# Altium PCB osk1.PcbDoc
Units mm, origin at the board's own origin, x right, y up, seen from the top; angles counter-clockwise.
Board outline 152.4 x 101.6 mm, 2 copper layers (Top Layer, Bottom Layer); 15 components, 15 nets, 59 pads, 0 vias.
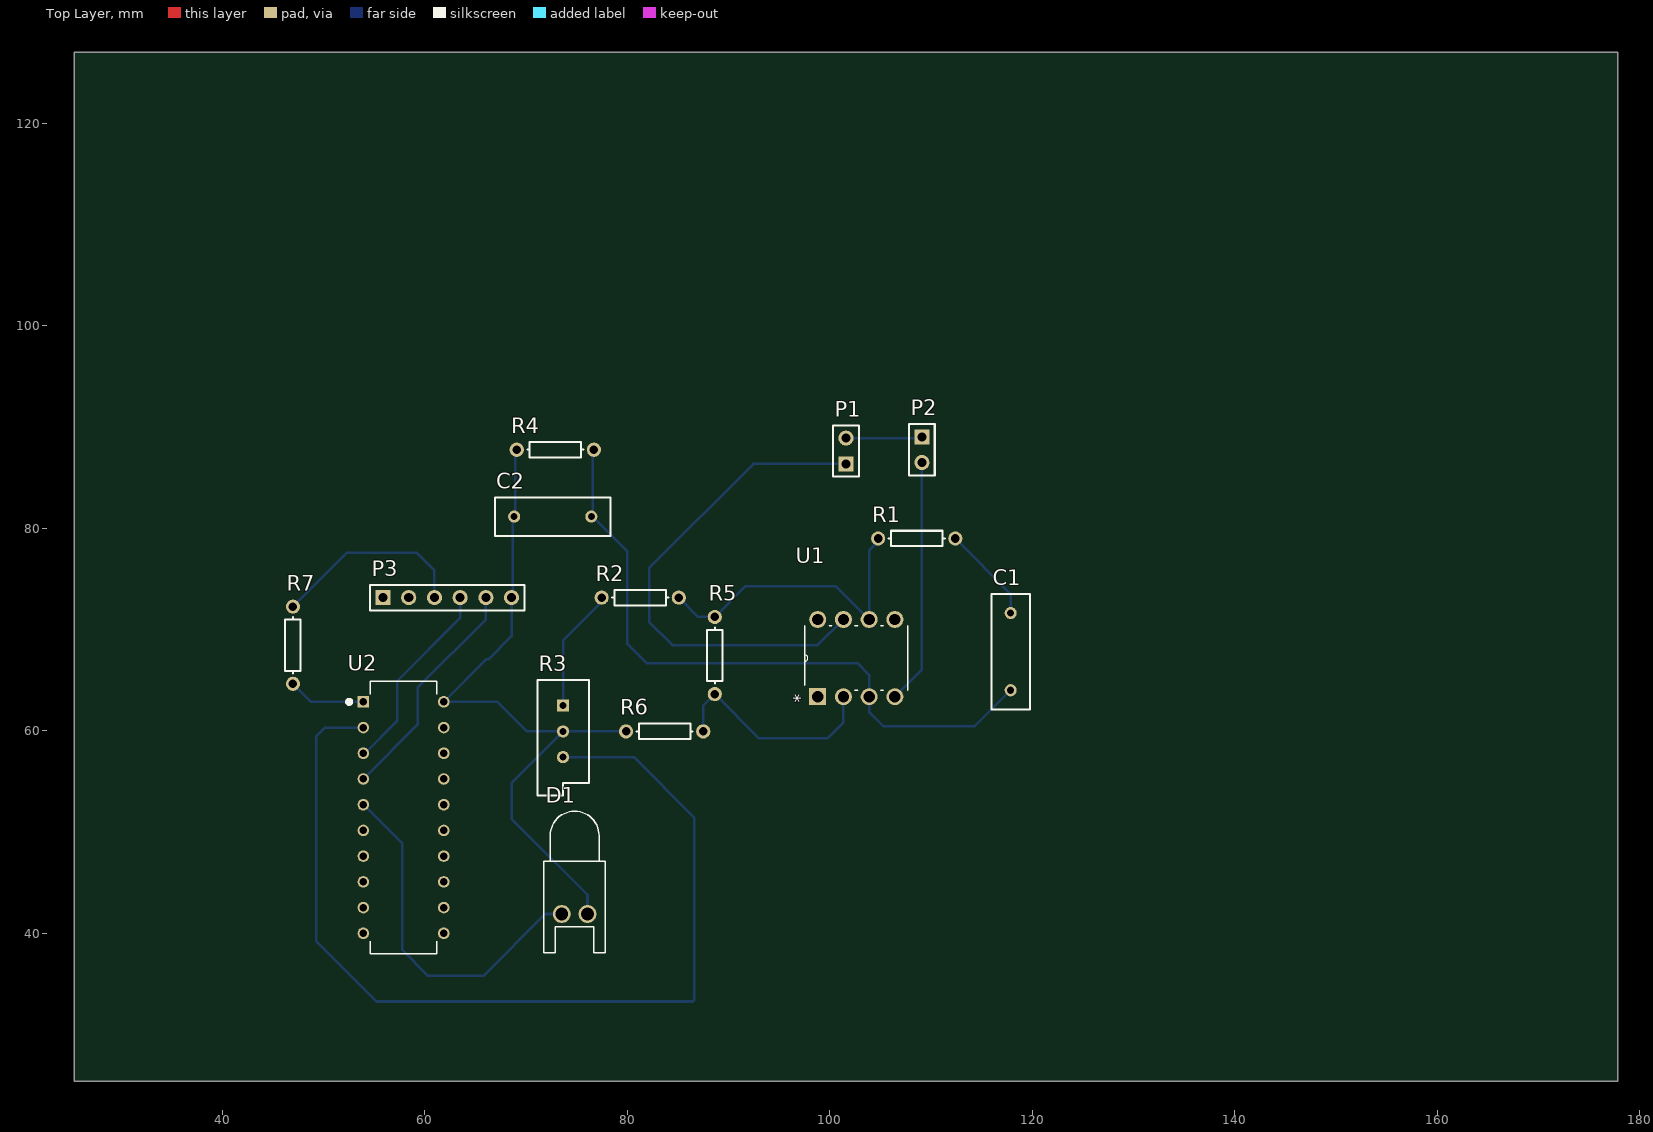
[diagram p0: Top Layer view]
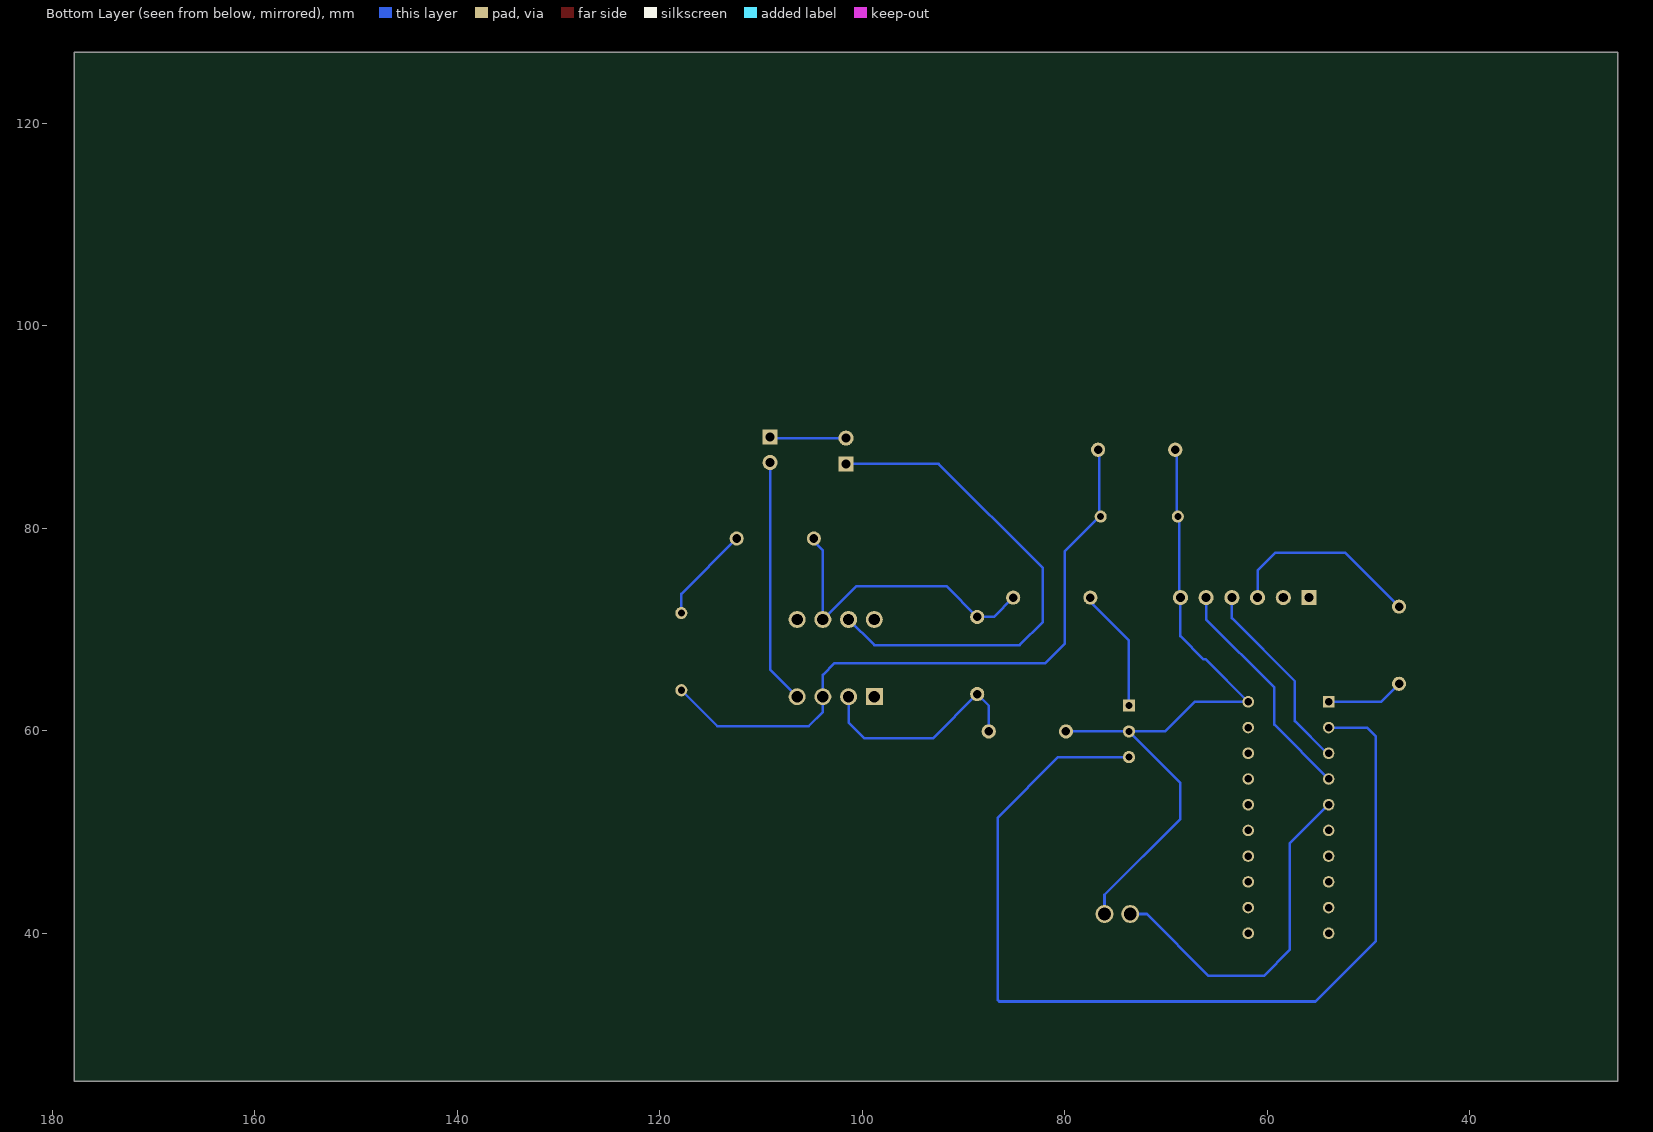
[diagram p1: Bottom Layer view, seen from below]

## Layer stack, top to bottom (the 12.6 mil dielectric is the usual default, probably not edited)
Top Solder: solder mask 0.0102, Solder Resist, Dk 3.5
Top Layer: signal copper 0.0356
Dielectric 1: dielectric 0.32, FR-4, Dk 4.8
Bottom Layer: signal copper 0.0356
Bottom Solder: solder mask 0.0102, Solder Resist, Dk 3.5

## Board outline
25.4,25.4 177.8,25.4 177.8,127 25.4,127

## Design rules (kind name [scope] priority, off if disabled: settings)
Clearance [All] p1: gap=0.254 ignorepadtopadclearanceinfootprint=FALSE except(0: Arc-Hole Track-Hole SMDPad-Hole THPad-Hole Via-Hole Fill-Hole Poly-Hole Region-Hole Text-Hole)
PolygonConnect [All] p1: connectstyle=Relief reliefconductorwidth=0.254 reliefentries=4 polygonreliefangle="90 Angle" airgapwidth=0.254
RoutingVias [All] p1: holewidth=0.711 width=1.27 viastyle="Through Hole" minholewidth=0.711 minwidth=1.27 maxholewidth=0.711 maxwidth=1.27
SolderMaskExpansion [All] p1: expansion=0.102 istentingtop=FALSE
Width [All] p1: maxlimit=0.254 minlimit=0.254 preferedwidth=0.254
30 further rules are at their usual default settings.

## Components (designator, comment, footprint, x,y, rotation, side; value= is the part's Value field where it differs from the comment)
C1 "Cap" RAD-0.3 117.856,67.818 r270 top value=1nF
C2 "Cap" RAD-0.3 72.644,81.153 r0 top value=1nF
D1 "LED0" LED-0 74.803,41.91 r180 top
P1 "Header 2" HDR1X2 101.6,86.36 r90 top
P2 "Header 2" HDR1X2 109.093,89.027 r270 top
P3 "Header 6" HDR1X6 55.88,73.152 r0 top
R1 "Res1" AXIAL-0.3 108.585,78.994 r0 top value=100K
R2 "Res1" AXIAL-0.3 81.28,73.152 r180 top value=2.2K
R3 "RPot" VR5 73.66,59.944 r270 top value=1K
R4 "Res1" AXIAL-0.3 72.898,87.757 r0 top value=100K
R5 "Res1" AXIAL-0.3 88.646,67.437 r270 top value=100K
R6 "Res1" AXIAL-0.3 83.693,59.944 r180 top value=47K
R7 "Res1" AXIAL-0.3 46.99,68.453 r90 top value=100K
U1 "LM741CN" DIP254P762X508-8 106.426,70.993 r90 top
U2 "MSP430G2553IN20" DIP794W45P254L2692H508Q20 57.912,51.435 r0 top

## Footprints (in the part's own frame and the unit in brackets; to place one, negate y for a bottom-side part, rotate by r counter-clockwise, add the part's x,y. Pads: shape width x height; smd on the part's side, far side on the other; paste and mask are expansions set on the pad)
AXIAL-0.3 [mm] "Axial Device, Thru-Hole; 2 Leads; 0.3 in Pin Spacing"
  round 1.4 hole 0.85: 1(-3.81,0) 2(3.81,0)
  silkscreen extent -2.77,-0.76 2.77,0.76
DIP254P762X508-8 [mil]
  rect 66x66 hole 44: 1(-300,300)
  round 66 hole 44: 2(-300,200) 3(-300,100) 4(-300,0) 5(0,0) 6(0,100) 7(0,200) 8(0,300)
  silkscreen extent -275,-50 -25,350, body extent -189,-215 189,215, height 200
DIP794W45P254L2692H508Q20 [mm]
  rect 1.14x1.14 hole 0.74: 1(-3.97,11.43)
  round 1.14 hole 0.74: 2(-3.97,8.89) 3(-3.97,6.35) 4(-3.97,3.81) 5(-3.97,1.27) 6(-3.97,-1.27) 7(-3.97,-3.81) 8(-3.97,-6.35) 9(-3.97,-8.89) 10(-3.97,-11.43) 11(3.97,-11.43) 12(3.97,-8.89) 13(3.97,-6.35) 14(3.97,-3.81) 15(3.97,-1.27) 16(3.97,1.27) 17(3.97,3.81) 18(3.97,6.35) 19(3.97,8.89) 20(3.97,11.43)
  silkscreen extent -5.57,-13.46 3.3,13.46
HDR1X2 [mm] "Connector; Header; 2 Position"
  rect 1.5x1.5 hole 0.9: 1(0,0)
  round 1.5 hole 0.9: 2(2.54,0)
  silkscreen extent -1.27,-1.27 3.81,1.27
HDR1X6 [mm] "Connector; Header; 6 Position"
  rect 1.5x1.5 hole 0.9: 1(0,0)
  round 1.5 hole 0.9: 2(2.54,0) 3(5.08,0) 4(7.62,0) 5(10.16,0) 6(12.7,0)
  silkscreen extent -1.27,-1.27 13.97,1.27
LED-0 [mil] "LED; 2 Leads"
  round 70 hole 50: 1(50,0) 2(-50,0)
  silkscreen extent -120,-400 120,150
RAD-0.3 [mm] "Radial Cap, Thru-Hole; 2 Leads; 0.3 in Pin Spacing"
  round 1.2 hole 0.7: 1(-3.81,0) 2(3.81,0)
  silkscreen extent -5.71,-1.91 5.71,1.91
VR5 [mm] "Thru-Hole; 3 Leads"
  rect 1.2x1.2 hole 0.7: 1(-2.54,0)
  round 1.2 hole 0.7: 2(0,0) 3(2.54,0)
  silkscreen extent -5.08,-2.54 6.35,2.54

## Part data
C1 C2: "Capacitor"
D1: "Typical INFRARED GaAs LED"
P1 P2: "Header, 2-Pin"
P3: "Header, 6-Pin"
R1 R2 R4 R5 R6 R7: "Resistor"
R3: "Potentiometer"
U1: "General Purpose Amplifier 1 Circuit 8-DIP", Package="DIP-8 ON Semiconductor"
U2: "MSP430G2x53, MSP430G2x13 Mixed Signal Microcontroller 20-PDIP -40 to 85", Package=None

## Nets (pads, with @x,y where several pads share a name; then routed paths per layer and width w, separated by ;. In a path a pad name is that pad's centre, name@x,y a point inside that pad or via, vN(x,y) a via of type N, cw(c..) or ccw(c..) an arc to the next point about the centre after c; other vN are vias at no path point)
GND: C2.1 D1.2 P3.6 R3.2 R4.1 R6.2 U2.20 | length 70.5
  Bottom Layer w0.254: R4.1 68.961,87.63 68.961,81.28 C2.1 68.707,81.026 68.707,73.279 P3.6 68.58,69.342 66.294,67.056 66.073,67.056 U2.20 67.183,62.865 70.104,59.944 R3.2 ; D1.2 76.073,43.815 68.58,51.308 68.58,54.864 R3.2 ; R6.2 R3.2
NetC1_1: C1.1 R1.2 | length 9.6
  Bottom Layer w0.254: R1.2 117.856,73.533 C1.1
NetC1_2: C1.2 C2.2 R4.2 U1.3 | length 65.7
  Bottom Layer w0.254: R4.2 76.581,87.63 76.581,81.28 C2.2 76.581,81.153 80.01,77.724 80.01,68.58 81.915,66.675 102.721,66.675 103.886,65.51 U1.3 103.886,61.849 105.283,60.452 114.3,60.452 C1.2
NetD1_1: D1.1 U2.5 | length 35.3
  Bottom Layer w0.254: U2.5 57.785,48.862 57.785,38.376 60.347,35.814 65.786,35.814 71.882,41.91 D1.1
NetP1_1: P1.1 U1.7 | length 50.2
  Bottom Layer w0.254: U1.7 98.806,68.453 84.455,68.453 82.169,70.739 82.169,76.073 92.456,86.36 P1.1
NetP1_2: P1.2 P2.1 | length 7.5
  Bottom Layer w0.254: P1.2 108.966,88.9 P2.1
NetP2_2: P2.2 U1.4 | length 24.2
  Bottom Layer w0.254: U1.4 109.093,66.04 P2.2
NetP3_3: P3.3 R7.2 | length 19.6
  Bottom Layer w0.254: R7.2 52.324,77.597 59.182,77.597 60.96,75.819 P3.3
NetP3_4: P3.4 U2.3 | length 19.4
  Bottom Layer w0.254: U2.3 54.102,57.785 57.277,60.96 57.277,64.897 63.5,71.12 P3.4
NetP3_5: P3.5 U2.4 | length 22.9
  Bottom Layer w0.254: U2.4 59.309,60.612 59.309,64.262 66.04,70.993 P3.5
NetR1_1: R1.1 R2.1 R5.1 U1.6 | length 30.6
  Bottom Layer w0.254: R2.1 86.995,71.247 R5.1 91.694,74.295 100.584,74.295 U1.6 103.886,77.81 104.775,78.699 R1.1
NetR2_2: R2.2 R3.1 | length 12.2
  Bottom Layer w0.254: R3.1 73.66,68.926 77.251,72.517 77.251,72.933 R2.2
NetR3_3: R3.3 U2.2 | length 98.5
  Bottom Layer w0.254: U2.2 50.165,60.325 49.276,59.436 49.276,39.243 49.425,39.094 55.245,33.274 86.465,33.274 86.614,33.423 86.614,51.435 80.645,57.404 R3.3
NetR5_2: R5.2 R6.1 U1.2 | length 21.9
  Bottom Layer w0.254: R6.1 87.503,62.484 R5.2 93.017,59.256 99.769,59.256 101.346,60.833 U1.2
NetR7_1: R7.1 U2.1 | length 7.7
  Bottom Layer w0.254: R7.1 48.768,62.865 U2.1
pads on no net: P3.1 P3.2 U1.1 U1.5 U1.8 U2.6 U2.7 U2.8 U2.9 U2.10 U2.11 U2.12 U2.13 U2.14 U2.15 U2.16 U2.17 U2.18 U2.19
